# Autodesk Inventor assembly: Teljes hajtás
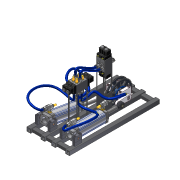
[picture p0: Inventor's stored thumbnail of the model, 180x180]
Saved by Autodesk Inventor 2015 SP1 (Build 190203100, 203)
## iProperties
Created: 2013-02
Part Number: Teljes hajtás
Document SubType Name: Assembly
Designer: Marci
Author: Marci
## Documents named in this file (19)
- I:\WS2015 CAD Data ANLAS\#01- Polymechanics and Automation\01 - 3D Models\Pneumatic System\Teljes hajtás.iam
- I:\WS2015 CAD Data ANLAS\#01- Polymechanics and Automation\01 - 3D Models\Pneumatic System\Váz.iam
- I:\WS2015 CAD Data ANLAS\#01- Polymechanics and Automation\01 - 3D Models\Pneumatic System\Közdarab.ipt
- I:\WS2015 CAD Data ANLAS\#01- Polymechanics and Automation\01 - 3D Models\Pneumatic System\Csapágy billenő felerősítéshez\Imported Components\1827001604\1827001604.ipt
- I:\WS2015 CAD Data ANLAS\#01- Polymechanics and Automation\01 - 3D Models\Pneumatic System\Billenőcsapos felerősítés\Imported Components\1827001611\1827001611.ipt
- I:\WS2015 CAD Data ANLAS\#01- Polymechanics and Automation\01 - 3D Models\Pneumatic System\csapágyház.ipt
- I:\WS2015 CAD Data ANLAS\#01- Polymechanics and Automation\01 - 3D Models\Pneumatic System\Összerakva a henger.iam
- I:\WS2015 CAD Data ANLAS\#01- Polymechanics and Automation\01 - 3D Models\Pneumatic System\Főtengely összerakva.iam
- I:\WS2015 CAD Data ANLAS\#01- Polymechanics and Automation\01 - 3D Models\Pneumatic System\Szelep összerakva.iam
- I:\WS2015 CAD Data ANLAS\#01- Polymechanics and Automation\01 - 3D Models\Pneumatic System\Szelep.ipt
- I:\WS2015 CAD Data ANLAS\#01- Polymechanics and Automation\01 - 3D Models\Pneumatic System\1.4 12 gyorscsat.ipt
- I:\WS2015 CAD Data ANLAS\#01- Polymechanics and Automation\01 - 3D Models\Pneumatic System\Zárócsavar.ipt
- I:\WS2015 CAD Data ANLAS\#01- Polymechanics and Automation\01 - 3D Models\Pneumatic System\Lemez.ipt
- I:\WS2015 CAD Data ANLAS\#01- Polymechanics and Automation\01 - 3D Models\Pneumatic System\Lemez 2.ipt
- I:\WS2015 CAD Data ANLAS\#01- Polymechanics and Automation\01 - 3D Models\Pneumatic System\Teljes hajtás\AIP\Tube and Pipe\Teljes hajtás.Tube and Pipe Runs05.iam
- I:\WS2015 CAD Data ANLAS\#01- Polymechanics and Automation\01 - 3D Models\Pneumatic System\Atuador.iam
- I:\WS2015 CAD Data ANLAS\#01- Polymechanics and Automation\01 - 3D Models\Pneumatic System\Eixo.ipt
- I:\WS2015 CAD Data ANLAS\#01- Polymechanics and Automation\01 - 3D Models\Pneumatic System\Ponta.ipt
- I:\WS2015 CAD Data ANLAS\#01- Polymechanics and Automation\01 - 3D Models\Pneumatic System\DIN 912 - M8 x 1,25 x 30 x 26,875.ipt
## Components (69 placed, 18 different names)
1. Váz:1 [sub-assembly] — Flush:1, Mate:1, Flush:2, Mate:2, Flush:3, Flush:4, Mate:3, Flush:5, Flush:6, Mate:4, Flush:7, Flush:8, Mate:14, Mate:15, Flush:17, Flush:18, Flush:19, Flush:20, Flush:25, Mate:30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
2. Közdarab:1 — Flush:1, Mate:1, Flush:2, Mate:5, Flush:9, Flush:10
3. Közdarab:2 — Mate:2, Flush:3, Flush:4, Mate:6, Flush:11, Flush:12
4. Közdarab:3 — Mate:3, Flush:5, Flush:6, Flush:13, Mate:7, Flush:14
5. Közdarab:4 — Mate:4, Flush:7, Flush:8, Mate:8, Flush:16
6. 1827001604:1 — Mate:5, Flush:9, Flush:10, Mate:12, Mate:13, Inserir:19, Inserir:22
7. 1827001604:2 — Mate:6, Flush:11, Flush:12, Mate:29, Inserir:20, Inserir:21
8. 1827001604:3 — Flush:13, Mate:7, Flush:14, Mate:9, Mate:10, Inserir:23, Inserir:24
9. 1827001604:4 — Mate:8, Flush:16, Mate:11, Inserir:25, Inserir:26
10. 1827001611:1 — Mate:9, Mate:10, Mate:11, Insert:15, Insert:16, Insert:17, Insert:18, Mate:67, Mate:68, Angle:2
11. 1827001611:2 — Mate:12, Mate:13, Mate:59, Mate:60, Angle:1, Insert:2, Insert:3, Insert:4, Insert:5
12. csapágyház:1 — Mate:14, Flush:18, Flush:20, Mate:22, Mate:23, Inserir:29, Inserir:30
13. csapágyház:2 — Mate:15, Flush:17, Flush:19, Inserir:27, Inserir:28
14. Összerakva a henger:1 [sub-assembly] — Mate:61, Mate:62, Mate:63
15. Összerakva a henger:2 [sub-assembly] — Mate:69, Mate:70, Mate:72
16. Főtengely összerakva:1 [sub-assembly] — Mate:22, Mate:23, Mate:65, Mate:71, MOTOR
17. Szelep összerakva:1 [sub-assembly] — Mate:28, Mate:29, Mate:30, Flush:27, Flush:28, Flush:30, Mate:55, Mate:56
18. Szelep összerakva:2 [sub-assembly] — Flush:26, Flush:27, Flush:28, Flush:29, Mate:58
19. Szelep:1 — Flush:31, Mate:31, Flush:32, Mate:34, Mate:35, Mate:36, Mate:38, Mate:40, Mate:42, Mate:44, Mate:47, Mate:48, Mate:51, Mate:54, Flush:34
20. Szelep:2 — Flush:29, Flush:30, Flush:31, Mate:31, Flush:32, Mate:32, Mate:33, Mate:37, Mate:39, Mate:41, Mate:43, Mate:45, Mate:46, Mate:49, Mate:50, Mate:52, Flush:33
21. 1.4 12 gyorscsat:1 — Mate:32, Mate:33
22. 1.4 12 gyorscsat:2 — Mate:34, Mate:35
23. 1.4 12 gyorscsat:3 — Mate:36, Mate:38
24. 1.4 12 gyorscsat:4 — Mate:37, Mate:39
25. Zárócsavar:1 — Mate:46, Mate:49
26. Zárócsavar:2 — Mate:47, Mate:48
27. Zárócsavar:3 — Mate:40, Mate:51
28. Zárócsavar:4 — Mate:41, Mate:50
29. Zárócsavar:5 — Mate:43, Mate:45
30. Zárócsavar:6 — Mate:42, Mate:44
31. Lemez:1 — Mate:52, Flush:33, Mate:53, Flush:35
32. Lemez:2 — Mate:54, Flush:34, Flush:35
33. Lemez 2:1 — Mate:55, Mate:56, Mate:57, Flush:36, Flush:37
34. Lemez 2:2 — Flush:36, Mate:58, Flush:37
35. Tube & Pipe Runs 05 [sub-assembly]
36. Atuador:1 [sub-assembly] — Mate:59, Mate:60, Mate:61, Mate:62, Mate:63, Angle:1, Mate:64, Insert:6, Insert:7, Insert:8, Insert:9
37. Eixo:1 — Mate:64, Insert:1
38. Ponta:1 — Insert:1, Mate:65
39. DIN 912 - M8 x 1,25 x 30 x 26,875:1 — Insert:2
40. DIN 912 - M8 x 1,25 x 30 x 26,875:2 — Insert:3
41. DIN 912 - M8 x 1,25 x 30 x 26,875:3 — Insert:4
42. DIN 912 - M8 x 1,25 x 30 x 26,875:4 — Insert:5
43. DIN 912 - M8 x 1,25 x 30 x 26,875:5 — Insert:6
44. DIN 912 - M8 x 1,25 x 30 x 26,875:6 — Insert:7
45. DIN 912 - M8 x 1,25 x 30 x 26,875:7 — Insert:9
46. DIN 912 - M8 x 1,25 x 30 x 26,875:8 — Insert:8
47. Atuador:2 [sub-assembly] — Mate:67, Mate:68, Mate:69, Mate:70, Angle:2, Mate:72
48. Eixo:2
49. Ponta:2 — Mate:71
50. DIN 912 - M8 x 1,25 x 30 x 26,875:9 — Insert:16
51. DIN 912 - M8 x 1,25 x 30 x 26,875:10 — Insert:17
52. DIN 912 - M8 x 1,25 x 30 x 26,875:11 — Insert:18
53. DIN 912 - M8 x 1,25 x 30 x 26,875:12 — Insert:15
54. DIN 912 - M8 x 1,25 x 30 x 26,875:13
55. DIN 912 - M8 x 1,25 x 30 x 26,875:14
56. DIN 912 - M8 x 1,25 x 30 x 26,875:15
57. DIN 912 - M8 x 1,25 x 30 x 26,875:16
58. DIN 912 - M8 x 1,25 x 30 x 26,875:17 — Inserir:19
59. DIN 912 - M8 x 1,25 x 30 x 26,875:18 — Inserir:23
60. DIN 912 - M8 x 1,25 x 30 x 26,875:19 — Inserir:20
61. DIN 912 - M8 x 1,25 x 30 x 26,875:20 — Inserir:21
62. DIN 912 - M8 x 1,25 x 30 x 26,875:21 — Inserir:22
63. DIN 912 - M8 x 1,25 x 30 x 26,875:22 — Inserir:24
64. DIN 912 - M8 x 1,25 x 30 x 26,875:23 — Inserir:25
65. DIN 912 - M8 x 1,25 x 30 x 26,875:24 — Inserir:26
66. DIN 912 - M8 x 1,25 x 30 x 26,875:25 — Inserir:29
67. DIN 912 - M8 x 1,25 x 30 x 26,875:26 — Inserir:30
68. DIN 912 - M8 x 1,25 x 30 x 26,875:27 — Inserir:27
69. DIN 912 - M8 x 1,25 x 30 x 26,875:28 — Inserir:28
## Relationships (121: Mate 61, Flush 32, Insert 25, Angle 3)
- Flush:1: Váz:1 ↔ Közdarab:1
- Mate:1: Váz:1 ↔ Közdarab:1
- Flush:2: Váz:1 ↔ Közdarab:1
- Mate:2: Váz:1 ↔ Közdarab:2
- Flush:3: Váz:1 ↔ Közdarab:2
- Flush:4: Váz:1 ↔ Közdarab:2
- Mate:3: Váz:1 ↔ Közdarab:3
- Flush:5: Váz:1 ↔ Közdarab:3
- Flush:6: Váz:1 ↔ Közdarab:3
- Mate:4: Váz:1 ↔ Közdarab:4
- Flush:7: Váz:1 ↔ Közdarab:4
- Flush:8: Váz:1 ↔ Közdarab:4
- Mate:5: Közdarab:1 ↔ 1827001604:1
- Flush:9: Közdarab:1 ↔ 1827001604:1
- Flush:10: Közdarab:1 ↔ 1827001604:1
- Mate:6: Közdarab:2 ↔ 1827001604:2
- Flush:11: Közdarab:2 ↔ 1827001604:2
- Flush:12: Közdarab:2 ↔ 1827001604:2
- Flush:13: Közdarab:3 ↔ 1827001604:3
- Mate:7: Közdarab:3 ↔ 1827001604:3
- Flush:14: Közdarab:3 ↔ 1827001604:3
- Mate:8: Közdarab:4 ↔ 1827001604:4
- Flush:16: Közdarab:4 ↔ 1827001604:4
- Mate:9: 1827001604:3 ↔ 1827001611:1
- Mate:10: 1827001604:3 ↔ 1827001611:1
- Mate:11: 1827001604:4 ↔ 1827001611:1
- Mate:12: 1827001604:1 ↔ 1827001611:2
- Mate:13: 1827001604:1 ↔ 1827001611:2
- Mate:14: Váz:1 ↔ csapágyház:1
- Mate:15: Váz:1 ↔ csapágyház:2
- Flush:17: Váz:1 ↔ csapágyház:2
- Flush:18: Váz:1 ↔ csapágyház:1
- Flush:19: Váz:1 ↔ csapágyház:2
- Flush:20: Váz:1 ↔ csapágyház:1
- Mate:22: csapágyház:1 ↔ Főtengely összerakva:1
- Mate:23: csapágyház:1 ↔ Főtengely összerakva:1
- Flush:25: Váz:1
- Mate:28: Szelep összerakva:1
- Mate:29: 1827001604:2 ↔ Szelep összerakva:1
- Mate:30: Váz:1 ↔ Szelep összerakva:1
- Flush:26: Szelep összerakva:2
- Flush:27: Szelep összerakva:1 ↔ Szelep összerakva:2
- Flush:28: Szelep összerakva:1 ↔ Szelep összerakva:2
- Flush:29: Szelep összerakva:2 ↔ Szelep:2
- Flush:30: Szelep összerakva:1 ↔ Szelep:2
- Flush:31: Szelep:1 ↔ Szelep:2
- Mate:31: Szelep:1 ↔ Szelep:2
- Flush:32: Szelep:1 ↔ Szelep:2
- Mate:32: Szelep:2 ↔ 1.4 12 gyorscsat:1
- Mate:33: Szelep:2 ↔ 1.4 12 gyorscsat:1
- Mate:34: Szelep:1 ↔ 1.4 12 gyorscsat:2
- Mate:35: Szelep:1 ↔ 1.4 12 gyorscsat:2
- Mate:36: Szelep:1 ↔ 1.4 12 gyorscsat:3
- Mate:37: Szelep:2 ↔ 1.4 12 gyorscsat:4
- Mate:38: Szelep:1 ↔ 1.4 12 gyorscsat:3
- Mate:39: Szelep:2 ↔ 1.4 12 gyorscsat:4
- Mate:40: Szelep:1 ↔ Zárócsavar:3
- Mate:41: Szelep:2 ↔ Zárócsavar:4
- Mate:42: Szelep:1 ↔ Zárócsavar:6
- Mate:43: Szelep:2 ↔ Zárócsavar:5
- Mate:44: Szelep:1 ↔ Zárócsavar:6
- Mate:45: Szelep:2 ↔ Zárócsavar:5
- Mate:46: Szelep:2 ↔ Zárócsavar:1
- Mate:47: Szelep:1 ↔ Zárócsavar:2
- Mate:48: Szelep:1 ↔ Zárócsavar:2
- Mate:49: Szelep:2 ↔ Zárócsavar:1
- Mate:50: Szelep:2 ↔ Zárócsavar:4
- Mate:51: Szelep:1 ↔ Zárócsavar:3
- Mate:52: Szelep:2 ↔ Lemez:1
- Flush:33: Szelep:2 ↔ Lemez:1
- Mate:53: Váz:1 ↔ Lemez:1
- Mate:54: Szelep:1 ↔ Lemez:2
- Flush:34: Szelep:1 ↔ Lemez:2
- Flush:35: Lemez:1 ↔ Lemez:2
- Mate:55: Szelep összerakva:1 ↔ Lemez 2:1
- Mate:56: Szelep összerakva:1 ↔ Lemez 2:1
- Mate:57: Váz:1 ↔ Lemez 2:1
- Flush:36: Lemez 2:1 ↔ Lemez 2:2
- Mate:58: Szelep összerakva:2 ↔ Lemez 2:2
- Flush:37: Lemez 2:1 ↔ Lemez 2:2
- Mate:59: 1827001611:2 ↔ Atuador:1
- Mate:60: 1827001611:2 ↔ Atuador:1
- Mate:61: Összerakva a henger:1 ↔ Atuador:1
- Mate:62: Összerakva a henger:1 ↔ Atuador:1
- Mate:63: Összerakva a henger:1 ↔ Atuador:1
- Angle:1: 1827001611:2 ↔ Atuador:1
- Mate:64: Atuador:1 ↔ Eixo:1
- Insert:1: Eixo:1 ↔ Ponta:1
- Mate:65: Főtengely összerakva:1 ↔ Ponta:1
- Insert:2: 1827001611:2 ↔ DIN 912 - M8 x 1,25 x 30 x 26,875:1
- Insert:3: 1827001611:2 ↔ DIN 912 - M8 x 1,25 x 30 x 26,875:2
- Insert:4: 1827001611:2 ↔ DIN 912 - M8 x 1,25 x 30 x 26,875:3
- Insert:5: 1827001611:2 ↔ DIN 912 - M8 x 1,25 x 30 x 26,875:4
- Insert:6: Atuador:1 ↔ DIN 912 - M8 x 1,25 x 30 x 26,875:5
- Insert:7: Atuador:1 ↔ DIN 912 - M8 x 1,25 x 30 x 26,875:6
- Insert:8: Atuador:1 ↔ DIN 912 - M8 x 1,25 x 30 x 26,875:8
- Insert:9: Atuador:1 ↔ DIN 912 - M8 x 1,25 x 30 x 26,875:7
- Insert:15: 1827001611:1 ↔ DIN 912 - M8 x 1,25 x 30 x 26,875:12
- Insert:16: 1827001611:1 ↔ DIN 912 - M8 x 1,25 x 30 x 26,875:9
- Insert:17: 1827001611:1 ↔ DIN 912 - M8 x 1,25 x 30 x 26,875:10
- Insert:18: 1827001611:1 ↔ DIN 912 - M8 x 1,25 x 30 x 26,875:11
- Mate:67: 1827001611:1 ↔ Atuador:2
- Mate:68: 1827001611:1 ↔ Atuador:2
- Mate:69: Összerakva a henger:2 ↔ Atuador:2
- Mate:70: Összerakva a henger:2 ↔ Atuador:2
- Mate:71: Főtengely összerakva:1 ↔ Ponta:2
- Angle:2: 1827001611:1 ↔ Atuador:2
- Mate:72: Összerakva a henger:2 ↔ Atuador:2
- MOTOR [Angle]: Váz:1 ↔ Főtengely összerakva:1
- Inserir:19: 1827001604:1 ↔ DIN 912 - M8 x 1,25 x 30 x 26,875:17
- Inserir:20: 1827001604:2 ↔ DIN 912 - M8 x 1,25 x 30 x 26,875:19
- Inserir:21: 1827001604:2 ↔ DIN 912 - M8 x 1,25 x 30 x 26,875:20
- Inserir:22: 1827001604:1 ↔ DIN 912 - M8 x 1,25 x 30 x 26,875:21
- Inserir:23: 1827001604:3 ↔ DIN 912 - M8 x 1,25 x 30 x 26,875:18
- Inserir:24: 1827001604:3 ↔ DIN 912 - M8 x 1,25 x 30 x 26,875:22
- Inserir:25: 1827001604:4 ↔ DIN 912 - M8 x 1,25 x 30 x 26,875:23
- Inserir:26: 1827001604:4 ↔ DIN 912 - M8 x 1,25 x 30 x 26,875:24
- Inserir:27: csapágyház:2 ↔ DIN 912 - M8 x 1,25 x 30 x 26,875:27
- Inserir:28: csapágyház:2 ↔ DIN 912 - M8 x 1,25 x 30 x 26,875:28
- Inserir:29: csapágyház:1 ↔ DIN 912 - M8 x 1,25 x 30 x 26,875:25
- Inserir:30: csapágyház:1 ↔ DIN 912 - M8 x 1,25 x 30 x 26,875:26
## Named parameters: d116_d105 = 0, d117_d106 = 0, d118_d112 = 0, d119_d113 = 0, d120_d114 = 0, d121_d115 = 0
